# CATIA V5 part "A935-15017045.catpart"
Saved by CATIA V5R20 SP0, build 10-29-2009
Part number: A935-15017045
Source: Unknown
Property "A": "110.000"
Property "ARTICLENO": "A935-15017045"
Property "B": "20.000"
Property "BOMINFO": "A935-15017045"
Property "CODE": "A935-15017045"
Property "L": "170.000"
Property "L1": "143.370"
Property "LINA": "A935-15017045"
Property "NB": "A935-15017045"
Property "NBSYN": "$CODE."
Property "NN": "A935"
Property "NT": "VDI 3357 H-Type Cam Drivers, steel (16MnCr5)"
Property "SUPPLIER": "CF"
Property "T": "45.000"
Property "W": "150.000"
Bounding box of the stored display mesh (mm): x 0 to 170, y 0 to 45, z -150 to 0
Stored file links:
  C:\Users\Utente\Desktop\3D files A935\A935-15017045.catpart
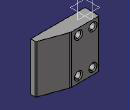
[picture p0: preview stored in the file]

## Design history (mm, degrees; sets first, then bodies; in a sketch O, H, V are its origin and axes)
Body1 "Geometry.1" (main body)
  Solid1 "A935-15017045.catpart": solid without history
